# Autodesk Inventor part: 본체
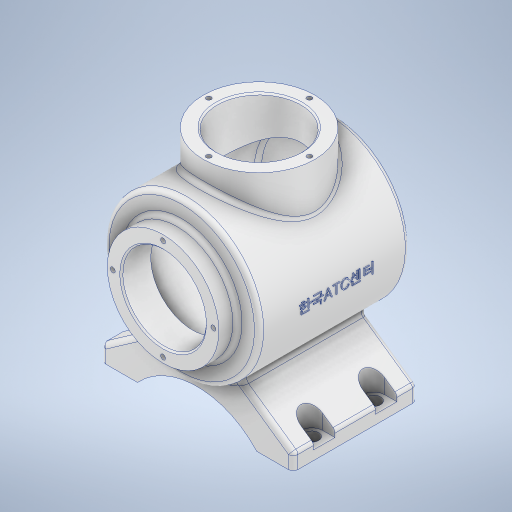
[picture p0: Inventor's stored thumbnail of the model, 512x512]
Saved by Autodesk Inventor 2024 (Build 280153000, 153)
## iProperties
Created: 2023-08
Part Number: 본체
Material: 알루미늄 6061
Document SubType Name: Modeling
Designer: Owner
Density: 2.7 g/cm^3
Appearance: 알루미늄 - 평지
Mass: 1296.71 g
Surface Area: 1060.44 cm^2
Volume: 480.264 cm^3
Author: Owner
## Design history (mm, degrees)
sketch "스케치1"
  geometry: L1 (36, 62)-(36, 50); L2 (36, 50)-(50, 50); L3 (50, 50)-(50, -46.336); L4 (0, 62)-(0, -58); L5 (43, -41.887)-(43, 43); L6 (43, 43)-(27, 43); L7 (27, 43)-(27, 62); L8 (36, 62)-(27, 62); A1 r 113 centre (0, 55) between (0, -58) and (50, -46.336); A2 r 106 centre (0, 55) between (0, -51) and (43, -41.887); 1 further point
  constraints: 16 end point, 4 perpendicular, 4 point on circle, 2 centre point, 2 point on line, 2 vertical, 1 horizontal, 1 horizontal alignment, 1 vertical alignment
  dimensions: "d0" = 120 vertical distance of L4.end L1.start; "d1" = 108 vertical distance of L4.end L2.end; "d2" = 113 radius of A1; "d3" = 100 diameter of L3 L4; "d4" = 72 diameter of L1 L4; "d5" = 62 distance of L4.start point (0, 0); "d6" = 7 radial gap between concentric circles of A1 A2; "d7" = 86 diameter of L5 L4; "d8" = 54 diameter of L7 L4; "d9" = 19 distance of L6.end L7.end
revolve "회전1" sketch "스케치1" stored, may be unused: angle "d10" = 90 deg
sketch "스케치2"
  geometry: L1 (62, -77)-(62, -67); L2 (62, -67)-(26.694, -42.278); L3 (-62, -77)-(-62, -67); L4 (-62, -67)-(-26.694, -42.278); L5 (-62, -77)-(-38.5, -77); L6 (38.5, -77)-(62, -77); A1 r 50 centre (0, 0) between (26.694, -42.278) and (-26.694, -42.278) reference; A2 r 52.096 centre (0, -112.096) between (38.5, -77) and (-38.5, -77); 2 further points
  constraints: 12 end point, 5 point on circle, 3 equal length, 2 horizontal, 2 horizontal alignment, 2 perpendicular, 1 centre point, 1 vertical, 1 vertical alignment
  dimensions: "d11" = 10 distance of L1.start L1.end; "d12" = 77 vertical distance of L1.start point (0, 0); "d13" = 55 deg angle of L2 L1; "d15" = 17 distance from line of point (0, -60) L6; "d16" = 77 distance of L6.start L5.end; "d17" = 124 distance between parallel lines of L1 L3
extrude "돌출1" join sketch "스케치2" stored distance "d18" = 80; taper "d19" = 0 deg
sketch "스케치3"
  geometry: L1 (-100.5, -80)-(-100.5, 0) reference; L2 (-100.5, 0)-(-77, 0) reference; C1 r 4.5 at (-92.5, -20); 1 further point
  constraints: 1 centre point
  dimensions: "d20" = 9 diameter of C1; "d21" = 8 distance from line of C1.centre L1; "d22" = 20 distance from line of C1.centre L2
extrude "돌출2" cut sketch "스케치3" stored distance "d23" = 0; taper "d24" = 0 deg
node "작업 평면1"
sketch "스케치4"
  geometry: L1 (-10.193, -20)-(8, -20); L2 (0, -27)-(8, -27); L3 (8, -13)-(0, -13); L4 (0, -80)-(0, 0) reference; L5 (0, 0)-(23.5, 0) reference; C1 r 4.5 at (8, -20) reference; A1 r 7 centre (8, -20) between (8, -27) and (8, -13); 2 further points
  constraints: 8 end point, 2 parallel, 2 point on circle, 2 point on line, 2 tangent, 1 centre point, 1 coincident, 1 horizontal, 1 midpoint
  dimensions: "d26" = 7 radius of A1
extrude "돌출3" cut sketch "스케치4" stored distance "d27" = 10; taper "d28" = 0 deg
sketch "스케치5"
  geometry: 2 further points
  constraints: 1 vertical alignment
  dimensions: "d29" = 32.5 distance of point (0, 0) point (0, 32.5)
hole "구멍1" sketch "스케치5" at (0, 32.5) diameter "d30" = 3.242; stored, may be unused: countersink angle "d34" = 90 deg, drill point angle "d36" = 118 deg; dims "d31" = 8, "d32" = 4, "d33" = 2, "d35" = 10
node "작업 평면2"
sketch "스케치6"
  geometry: C1 r 36 at (0, 0); 1 further point
  constraints: 1 centre point, 1 coincident
  dimensions: "d41" = 72 diameter of C1
extrude "돌출4" join sketch "스케치6" stored distance "d42" = 10; taper "d43" = 0 deg
sketch "스케치7"
  geometry: C1 r 27 at (0, 0); 1 further point
  constraints: 1 centre point, 1 coincident
  dimensions: "d44" = 54 diameter of C1
extrude "돌출5" cut sketch "스케치7" stored distance "d45" = 10; taper "d46" = 0 deg
sketch "스케치8"
  geometry: 2 further points
  constraints: 1 horizontal alignment
  dimensions: "d47" = 32.5 distance of point (0, 0) point (-32.5, 0)
hole "구멍2" sketch "스케치8" at (-32.5, 0) diameter "d48" = 3.242; stored, may be unused: countersink angle "d52" = 90 deg, drill point angle "d54" = 118 deg; dims "d49" = 8, "d50" = 4, "d51" = 2, "d53" = 10
node "작업 평면3"
sketch "스케치9"
  geometry: L1 (-36, 60.168)-(36, 60.168) reference; 2 further points
  constraints: 1 coincident, 1 other
feature "엠보싱1" sketch "스케치9" dims "d0" = 120, "d1" = 108, "d2" = 113, "d3" = 100, "d4" = 72, "d5" = 62, "d6" = 7, "d7" = 86, "d8" = 54, "d9" = 19, "d11" = 10, "d12" = 77, "d13" = 55 deg, "d15" = 17, "d16" = 77, "d17" = 124, "d59" = 0.5, "d60" = 0
fillet "모깎기1" dims "d61" = 3
chamfer "모따기1" distance "d62" = 1; stored, may be unused: second distance "d63" = 2, angle "d64" = 45 deg
fillet "모깎기2" dims "d65" = 3
fillet "모깎기3" dims "d66" = 3
fillet "모깎기4" dims "d67" = 3
fillet "모깎기5" dims "d68" = 3
node "솔리드1"
mirror "미러1"
mirror "미러2"
pattern_circular "원형 패턴1" dims angle "d38" = 360 deg
pattern_circular "원형 패턴2" dims angle "d56" = 360 deg
feature "A9D066F2-1C7D-4E18-AEED-F7BC21143FA4" dims "d30" = 3.242, "d31" = 8, "d32" = 4, "d33" = 2, "d34" = 90 deg, "d35" = 10, "d36" = 118 deg
other parameters: "d25" = -6, "d40" = 65
